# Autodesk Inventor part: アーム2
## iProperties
Created: 2008-02
Part Number: アーム2
Document SubType Name: Modeling
Designer: y-shimazaki
Density: 1 g/cm^3
Author: y-shimazaki
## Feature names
1. 押し出し1 [Extrusion]
2. 押し出し2 [Extrusion]
3. 押し出し3 [Extrusion]
4. 押し出し4 [Extrusion]
5. 押し出し5 [Extrusion]
